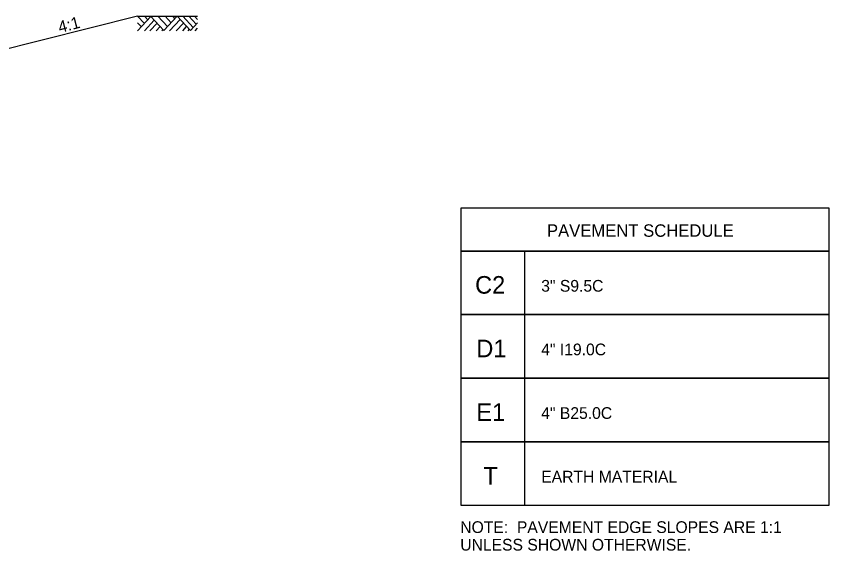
# Model space of a CAD drawing. Extents: x 1901582 to 1902252, y 193723 to 194156.
# Drawn here: x 1902084.43 to 1902129.68, y 193723.18 to 193752.96 of the extents above; entities that cross this region are included whole.
import ezdxf

# ---------------------------------------------------------------- set-up
doc = ezdxf.new("R2010")
doc.units = 0
for name, color, linetype in [('Old_Level_1', 7, 'Continuous'), ('Old_Level_11', 7, 'Continuous'), ('Old_Level_21', 7, 'Continuous'), ('Prop Pavement Schedule Description CELL', 7, 'Continuous')]:
    doc.layers.add(name, color=color, linetype=linetype)

msp = doc.modelspace()

# ---------------------------------------------------------------- linework, layer by layer
at = {"layer": 'Old_Level_1'}
for points in [[(1902091.192, 193752.959), (1902083.192, 193750.959)], [(1902091.192, 193752.959), (1902094.534, 193752.959)]]:
    msp.add_lwpolyline(points, dxfattribs=at)
at = {"layer": 'Old_Level_11'}
for p, q in [((1902091.192, 193752.959), (1902091.567, 193752.556)), ((1902091.192, 193752.154), (1902091.934, 193752.951)), ((1902091.566, 193752.154), (1902092.12, 193752.75)), ((1902091.567, 193752.959), (1902091.754, 193752.758)), ((1902091.934, 193752.951), (1902092.658, 193752.172)), ((1902092.325, 193752.959), (1902092.858, 193752.386)), ((1902092.658, 193752.172), (1902093.389, 193752.958)), ((1902092.723, 193752.959), (1902093.056, 193752.6)), ((1902092.968, 193752.154), (1902093.554, 193752.782)), ((1902093.125, 193752.959), (1902093.258, 193752.816)), ((1902093.389, 193752.958), (1902094.13, 193752.162)), ((1902093.711, 193752.959), (1902094.291, 193752.336)), ((1902094.044, 193752.959), (1902094.458, 193752.515)), ((1902094.364, 193752.959), (1902094.534, 193752.776)), ((1902091.192, 193752.597), (1902091.398, 193752.375)), ((1902091.875, 193752.154), (1902092.276, 193752.583)), ((1902092.222, 193752.154), (1902092.449, 193752.397)), ((1902093.338, 193752.154), (1902093.738, 193752.583)), ((1902093.704, 193752.154), (1902093.921, 193752.387)), ((1902094.13, 193752.162), (1902094.534, 193752.597)), ((1902094.4, 193752.154), (1902094.534, 193752.297)), ((1902092.533, 193752.154), (1902092.604, 193752.23)), ((1902093.999, 193752.154), (1902094.068, 193752.228))]:
    msp.add_line(p, q, dxfattribs=at)
at = {"layer": 'Prop Pavement Schedule Description CELL'}
msp.add_lwpolyline([(1902109.217, 193742.285), (1902129.679, 193742.285), (1902129.679, 193739.882), (1902109.217, 193739.882)], close=True, dxfattribs=at)
for points in [[(1902112.761, 193736.338), (1902109.217, 193736.338), (1902109.217, 193739.882), (1902129.679, 193739.882), (1902129.679, 193736.338), (1902112.761, 193736.338), (1902112.761, 193739.882)], [(1902112.761, 193732.794), (1902109.217, 193732.794), (1902109.217, 193736.338), (1902129.679, 193736.338), (1902129.679, 193732.794), (1902112.761, 193732.794), (1902112.761, 193736.338)], [(1902112.761, 193729.251), (1902109.217, 193729.251), (1902109.217, 193732.794), (1902129.679, 193732.794), (1902129.679, 193729.251), (1902112.761, 193729.251), (1902112.761, 193732.794)], [(1902112.761, 193725.707), (1902109.217, 193725.707), (1902109.217, 193729.251), (1902129.679, 193729.251), (1902129.679, 193725.707), (1902112.761, 193725.707), (1902112.761, 193729.251)]]:
    msp.add_lwpolyline(points, dxfattribs=at)

# ---------------------------------------------------------------- texts
at = {"layer": 'Old_Level_1'}
msp.add_text('4:1', height=0.656, rotation=14.7544, dxfattribs=at).set_placement((1902086.858, 193752.018))
at = {"layer": 'Old_Level_21'}
for s, height, p in [('C2', 0.98, (1902109.985, 193737.506)), ('3" S9.5C', 0.653, (1902113.667, 193737.616)), ('D1', 0.98, (1902110.055, 193733.962)), ('4" I19.0C', 0.653, (1902113.667, 193734.072)), ('E1', 0.98, (1902110.055, 193730.418)), ('4" B25.0C', 0.653, (1902113.667, 193730.529)), ('T', 0.98, (1902110.443, 193726.875)), ('EARTH MATERIAL', 0.653, (1902113.667, 193726.985)), ('NOTE:  PAVEMENT EDGE SLOPES ARE 1:1', 0.653, (1902109.158, 193724.174)), ('UNLESS SHOWN OTHERWISE.', 0.653, (1902109.158, 193723.194))]:
    msp.add_text(s, height=height, dxfattribs=at).set_placement(p)
at = {"layer": 'Prop Pavement Schedule Description CELL'}
msp.add_text('PAVEMENT SCHEDULE', height=0.69299, dxfattribs=at).set_placement((1902113.987, 193740.675))

doc.saveas('drawing.dxf')
